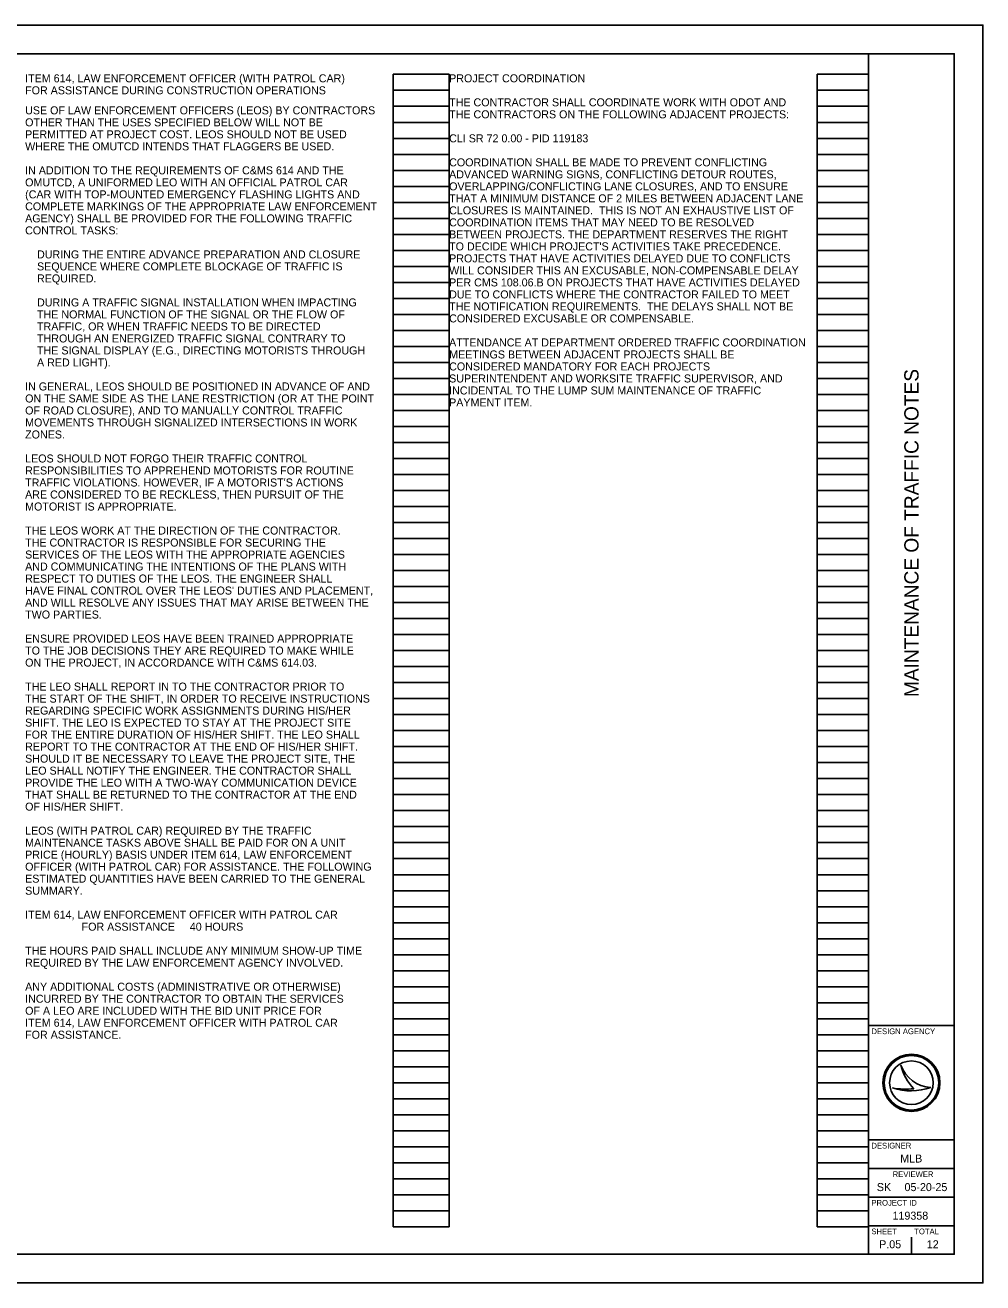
# Model space of a CAD drawing. Extents: x 0 to 34, y 0 to 22.
# Drawn here: x 17.24 to 34, y 0 to 22 of the extents above; entities that cross this region are included whole.
import ezdxf

# ---------------------------------------------------------------- set-up
doc = ezdxf.new("R2010")
doc.units = 0
for name, color, linetype in [('SH_Border', 7, 'Continuous'), ('SH_Cut_Line', 7, 'Continuous'), ('SH_Data', 7, 'Continuous'), ('SH_Text', 7, 'Continuous')]:
    doc.layers.add(name, color=color, linetype=linetype)

msp = doc.modelspace()

# ---------------------------------------------------------------- linework, layer by layer
at = {"layer": 'SH_Border'}
for p, q in [((32, 0.5), (32, 21.5)), ((32, 4.5), (33.5, 4.5)), ((32, 2.5), (33.5, 2.5)), ((32, 2), (33.5, 2)), ((32, 1.5), (33.5, 1.5)), ((32, 1), (33.5, 1))]:
    msp.add_line(p, q, dxfattribs=at)
msp.add_lwpolyline([(1.5, 21.5), (33.5, 21.5), (33.5, 0.5), (1.5, 0.5)], close=True, dxfattribs=at)
at = {"layer": 'SH_Cut_Line'}
msp.add_lwpolyline([(0, 0), (34, 0), (34, 22), (0, 22)], close=True, dxfattribs=at)
at = {"layer": 'SH_Data'}
for p, q in [((23.68, 0.98), (23.68, 21.14)), ((23.68, 21.14), (24.66, 21.14)), ((24.66, 0.98), (24.66, 21.14)), ((31.1, 0.98), (31.1, 21.14)), ((31.1, 21.14), (32, 21.14)), ((32, 0.98), (32, 21.14)), ((23.68, 20.86), (24.66, 20.86)), ((31.1, 20.86), (32, 20.86)), ((23.68, 20.58), (24.66, 20.58)), ((31.1, 20.58), (32, 20.58)), ((23.68, 20.3), (24.66, 20.3)), ((31.1, 20.3), (32, 20.3)), ((23.68, 20.02), (24.66, 20.02)), ((31.1, 20.02), (32, 20.02)), ((23.68, 19.74), (24.66, 19.74)), ((31.1, 19.74), (32, 19.74)), ((23.68, 19.46), (24.66, 19.46)), ((31.1, 19.46), (32, 19.46)), ((23.68, 19.18), (24.66, 19.18)), ((31.1, 19.18), (32, 19.18)), ((23.68, 18.9), (24.66, 18.9)), ((31.1, 18.9), (32, 18.9)), ((23.68, 18.62), (24.66, 18.62)), ((31.1, 18.62), (32, 18.62)), ((23.68, 18.34), (24.66, 18.34)), ((31.1, 18.34), (32, 18.34)), ((23.68, 18.06), (24.66, 18.06)), ((31.1, 18.06), (32, 18.06)), ((23.68, 17.78), (24.66, 17.78)), ((31.1, 17.78), (32, 17.78)), ((23.68, 17.5), (24.66, 17.5)), ((31.1, 17.5), (32, 17.5)), ((23.68, 17.22), (24.66, 17.22)), ((31.1, 17.22), (32, 17.22)), ((23.68, 16.94), (24.66, 16.94)), ((31.1, 16.94), (32, 16.94)), ((23.68, 16.66), (24.66, 16.66)), ((31.1, 16.66), (32, 16.66)), ((23.68, 16.38), (24.66, 16.38)), ((31.1, 16.38), (32, 16.38)), ((23.68, 16.1), (24.66, 16.1)), ((31.1, 16.1), (32, 16.1)), ((23.68, 15.82), (24.66, 15.82)), ((31.1, 15.82), (32, 15.82)), ((23.68, 15.54), (24.66, 15.54)), ((31.1, 15.54), (32, 15.54)), ((23.68, 15.26), (24.66, 15.26)), ((31.1, 15.26), (32, 15.26)), ((23.68, 14.98), (24.66, 14.98)), ((31.1, 14.98), (32, 14.98)), ((23.68, 14.7), (24.66, 14.7)), ((31.1, 14.7), (32, 14.7)), ((23.68, 14.42), (24.66, 14.42)), ((31.1, 14.42), (32, 14.42)), ((23.68, 14.14), (24.66, 14.14)), ((31.1, 14.14), (32, 14.14)), ((23.68, 13.86), (24.66, 13.86)), ((31.1, 13.86), (32, 13.86)), ((23.68, 13.58), (24.66, 13.58)), ((31.1, 13.58), (32, 13.58)), ((23.68, 13.3), (24.66, 13.3)), ((31.1, 13.3), (32, 13.3)), ((23.68, 13.02), (24.66, 13.02)), ((31.1, 13.02), (32, 13.02)), ((23.68, 12.74), (24.66, 12.74)), ((31.1, 12.74), (32, 12.74)), ((23.68, 12.46), (24.66, 12.46)), ((31.1, 12.46), (32, 12.46)), ((23.68, 12.18), (24.66, 12.18)), ((31.1, 12.18), (32, 12.18)), ((23.68, 11.9), (24.66, 11.9)), ((31.1, 11.9), (32, 11.9)), ((23.68, 11.62), (24.66, 11.62)), ((31.1, 11.62), (32, 11.62)), ((23.68, 11.34), (24.66, 11.34)), ((31.1, 11.34), (32, 11.34)), ((23.68, 11.06), (24.66, 11.06)), ((31.1, 11.06), (32, 11.06)), ((23.68, 10.78), (24.66, 10.78)), ((31.1, 10.78), (32, 10.78)), ((23.68, 10.5), (24.66, 10.5)), ((31.1, 10.5), (32, 10.5)), ((23.68, 10.22), (24.66, 10.22)), ((31.1, 10.22), (32, 10.22)), ((23.68, 9.94), (24.66, 9.94)), ((31.1, 9.94), (32, 9.94)), ((23.68, 9.66), (24.66, 9.66)), ((31.1, 9.66), (32, 9.66)), ((23.68, 9.38), (24.66, 9.38)), ((31.1, 9.38), (32, 9.38)), ((23.68, 9.1), (24.66, 9.1)), ((31.1, 9.1), (32, 9.1)), ((23.68, 8.82), (24.66, 8.82)), ((31.1, 8.82), (32, 8.82)), ((23.68, 8.54), (24.66, 8.54)), ((31.1, 8.54), (32, 8.54)), ((23.68, 8.26), (24.66, 8.26)), ((31.1, 8.26), (32, 8.26)), ((23.68, 7.98), (24.66, 7.98)), ((31.1, 7.98), (32, 7.98)), ((23.68, 7.7), (24.66, 7.7)), ((31.1, 7.7), (32, 7.7)), ((23.68, 7.42), (24.66, 7.42)), ((31.1, 7.42), (32, 7.42)), ((23.68, 7.14), (24.66, 7.14)), ((31.1, 7.14), (32, 7.14)), ((23.68, 6.86), (24.66, 6.86)), ((31.1, 6.86), (32, 6.86)), ((23.68, 6.58), (24.66, 6.58)), ((31.1, 6.58), (32, 6.58)), ((23.68, 6.3), (24.66, 6.3)), ((31.1, 6.3), (32, 6.3)), ((23.68, 6.02), (24.66, 6.02)), ((31.1, 6.02), (32, 6.02)), ((23.68, 5.74), (24.66, 5.74)), ((31.1, 5.74), (32, 5.74)), ((23.68, 5.46), (24.66, 5.46)), ((31.1, 5.46), (32, 5.46)), ((23.68, 5.18), (24.66, 5.18)), ((31.1, 5.18), (32, 5.18)), ((23.68, 4.9), (24.66, 4.9)), ((31.1, 4.9), (32, 4.9)), ((23.68, 4.62), (24.66, 4.62)), ((31.1, 4.62), (32, 4.62)), ((23.68, 4.34), (24.66, 4.34)), ((31.1, 4.34), (32, 4.34)), ((23.68, 4.06), (24.66, 4.06)), ((31.1, 4.06), (32, 4.06)), ((23.68, 3.78), (24.66, 3.78)), ((31.1, 3.78), (32, 3.78)), ((32.567, 3.81), (32.567, 3.81)), ((23.68, 3.5), (24.66, 3.5)), ((31.1, 3.5), (32, 3.5)), ((32.417, 3.41), (32.417, 3.41)), ((32.75, 3.5), (32.75, 3.5)), ((33.087, 3.419), (33.087, 3.419)), ((23.68, 3.22), (24.66, 3.22)), ((31.1, 3.22), (32, 3.22)), ((23.68, 2.94), (24.66, 2.94)), ((31.1, 2.94), (32, 2.94)), ((23.68, 2.66), (24.66, 2.66)), ((31.1, 2.66), (32, 2.66)), ((23.68, 2.38), (24.66, 2.38)), ((31.1, 2.38), (32, 2.38)), ((23.68, 2.1), (24.66, 2.1)), ((31.1, 2.1), (32, 2.1)), ((23.68, 1.82), (24.66, 1.82)), ((31.1, 1.82), (32, 1.82)), ((23.68, 1.54), (24.66, 1.54)), ((31.1, 1.54), (32, 1.54)), ((23.68, 1.26), (24.66, 1.26)), ((31.1, 1.26), (32, 1.26)), ((23.68, 0.98), (24.66, 0.98)), ((31.1, 0.98), (32, 0.98)), ((32.375, 0.675), (32.375, 0.675)), ((32.75, 0.5), (32.75, 0.8))]:
    msp.add_line(p, q, dxfattribs=at)
for radius in [0.5, 0.477, 0.477, 0.382]:
    msp.add_circle((32.75, 3.5), radius, dxfattribs=at)
for centre, radius, start, end in [((33.116, 3.998), 0.58, 198.9257, 198.9319), ((33.347, 3.97), 0.796, 191.6379, 191.6421), ((33.116, 3.998), 0.58, 198.9319, 267.1657), ((33.347, 3.97), 0.796, 191.6421, 226.0947), ((32.739, 4.37), 1.013, 251.4576, 290.0832), ((32.648, 4.654), 1.266, 259.4964, 259.4995), ((32.739, 4.37), 1.013, 251.4527, 251.4576), ((32.648, 4.654), 1.266, 259.4995, 276.6672)]:
    msp.add_arc(centre, radius, start, end, dxfattribs=at)

# ---------------------------------------------------------------- texts
msp.add_text('MAINTENANCE OF TRAFFIC NOTES', height=0.25, rotation=90, dxfattribs=at).set_placement((32.875, 10.247))
for s, height, p in [('DESIGN AGENCY', 0.1, (32.05, 4.35)), ('DESIGNER', 0.1, (32.05, 2.35)), ('MLB', 0.14, (32.554, 2.105)), ('REVIEWER', 0.1, (32.422, 1.85)), ('SK', 0.14, (32.145, 1.605)), ('05-20-25', 0.14, (32.629, 1.605)), ('PROJECT ID', 0.1, (32.05, 1.35)), ('119358', 0.14, (32.419, 1.105)), ('SHEET', 0.1, (32.05, 0.85)), ('TOTAL', 0.1, (32.8, 0.85)), ('P.05', 0.14, (32.185, 0.605)), ('12', 0.14, (33.019, 0.605))]:
    msp.add_text(s, height=height, dxfattribs=at).set_placement(p)
at = {"layer": 'SH_Text'}
for s, p in [('ITEM 614, LAW ENFORCEMENT OFFICER (WITH PATROL CAR)', (17.24, 21)), ('PROJECT COORDINATION', (24.66, 21)), ('FOR ASSISTANCE DURING CONSTRUCTION OPERATIONS', (17.24, 20.79)), ('THE CONTRACTOR SHALL COORDINATE WORK WITH ODOT AND ', (24.66, 20.58)), ('USE OF LAW ENFORCEMENT OFFICERS (LEOS) BY CONTRACTORS', (17.24, 20.44)), ('THE CONTRACTORS ON THE FOLLOWING ADJACENT PROJECTS:', (24.66, 20.37)), ('OTHER THAN THE USES SPECIFIED BELOW WILL NOT BE', (17.24, 20.23)), ('PERMITTED AT PROJECT COST. LEOS SHOULD NOT BE USED', (17.24, 20.02)), ('CLI SR 72 0.00 - PID 119183', (24.66, 19.95)), ('WHERE THE OMUTCD INTENDS THAT FLAGGERS BE USED.', (17.24, 19.81)), ('COORDINATION SHALL BE MADE TO PREVENT CONFLICTING ', (24.66, 19.53)), ('IN ADDITION TO THE REQUIREMENTS OF C&MS 614 AND THE', (17.24, 19.39)), ('ADVANCED WARNING SIGNS, CONFLICTING DETOUR ROUTES, ', (24.66, 19.32)), ('OMUTCD, A UNIFORMED LEO WITH AN OFFICIAL PATROL CAR', (17.24, 19.18)), ('OVERLAPPING/CONFLICTING LANE CLOSURES, AND TO ENSURE ', (24.66, 19.11)), ('(CAR WITH TOP-MOUNTED EMERGENCY FLASHING LIGHTS AND', (17.24, 18.97)), ('THAT A MINIMUM DISTANCE OF 2 MILES BETWEEN ADJACENT LANE ', (24.66, 18.9)), ('COMPLETE MARKINGS OF THE APPROPRIATE LAW ENFORCEMENT', (17.24, 18.76)), ('CLOSURES IS MAINTAINED.  THIS IS NOT AN EXHAUSTIVE LIST OF ', (24.66, 18.69)), ('AGENCY) SHALL BE PROVIDED FOR THE FOLLOWING TRAFFIC', (17.24, 18.55)), ('CONTROL TASKS:', (17.24, 18.34)), ('COORDINATION ITEMS THAT MAY NEED TO BE RESOLVED ', (24.66, 18.48)), ('BETWEEN PROJECTS. THE DEPARTMENT RESERVES THE RIGHT ', (24.66, 18.27)), ('    DURING THE ENTIRE ADVANCE PREPARATION AND CLOSURE', (17.24, 17.92)), ("TO DECIDE WHICH PROJECT'S ACTIVITIES TAKE PRECEDENCE.  ", (24.66, 18.06)), ('    SEQUENCE WHERE COMPLETE BLOCKAGE OF TRAFFIC IS', (17.24, 17.71)), ('PROJECTS THAT HAVE ACTIVITIES DELAYED DUE TO CONFLICTS ', (24.66, 17.85)), ('    REQUIRED.', (17.24, 17.5)), ('WILL CONSIDER THIS AN EXCUSABLE, NON-COMPENSABLE DELAY ', (24.66, 17.64)), ('PER CMS 108.06.B ON PROJECTS THAT HAVE ACTIVITIES DELAYED ', (24.66, 17.43)), ('    DURING A TRAFFIC SIGNAL INSTALLATION WHEN IMPACTING', (17.24, 17.08)), ('DUE TO CONFLICTS WHERE THE CONTRACTOR FAILED TO MEET ', (24.66, 17.22)), ('    THE NORMAL FUNCTION OF THE SIGNAL OR THE FLOW OF', (17.24, 16.87)), ('THE NOTIFICATION REQUIREMENTS.  THE DELAYS SHALL NOT BE ', (24.66, 17.01)), ('CONSIDERED EXCUSABLE OR COMPENSABLE.', (24.66, 16.8)), ('    TRAFFIC, OR WHEN TRAFFIC NEEDS TO BE DIRECTED', (17.24, 16.66)), ('    THROUGH AN ENERGIZED TRAFFIC SIGNAL CONTRARY TO', (17.24, 16.45)), ('ATTENDANCE AT DEPARTMENT ORDERED TRAFFIC COORDINATION ', (24.66, 16.38)), ('    THE SIGNAL DISPLAY (E.G., DIRECTING MOTORISTS THROUGH', (17.24, 16.24)), ('MEETINGS BETWEEN ADJACENT PROJECTS SHALL BE ', (24.66, 16.17)), ('    A RED LIGHT).', (17.24, 16.03)), ('CONSIDERED MANDATORY FOR EACH PROJECTS ', (24.66, 15.96)), ('SUPERINTENDENT AND WORKSITE TRAFFIC SUPERVISOR, AND ', (24.66, 15.75)), ('IN GENERAL, LEOS SHOULD BE POSITIONED IN ADVANCE OF AND', (17.24, 15.61)), ('INCIDENTAL TO THE LUMP SUM MAINTENANCE OF TRAFFIC ', (24.66, 15.54)), ('ON THE SAME SIDE AS THE LANE RESTRICTION (OR AT THE POINT', (17.24, 15.4)), ('PAYMENT ITEM.', (24.66, 15.33)), ('OF ROAD CLOSURE), AND TO MANUALLY CONTROL TRAFFIC', (17.24, 15.19)), ('MOVEMENTS THROUGH SIGNALIZED INTERSECTIONS IN WORK', (17.24, 14.98)), ('ZONES.', (17.24, 14.77)), ('LEOS SHOULD NOT FORGO THEIR TRAFFIC CONTROL', (17.24, 14.35)), ('RESPONSIBILITIES TO APPREHEND MOTORISTS FOR ROUTINE', (17.24, 14.14)), ('ARE CONSIDERED TO BE RECKLESS, THEN PURSUIT OF THE', (17.24, 13.72)), ("TRAFFIC VIOLATIONS. HOWEVER, IF A MOTORIST'S ACTIONS", (17.24, 13.93)), ('MOTORIST IS APPROPRIATE.', (17.24, 13.51)), ('THE LEOS WORK AT THE DIRECTION OF THE CONTRACTOR.', (17.24, 13.09)), ('THE CONTRACTOR IS RESPONSIBLE FOR SECURING THE', (17.24, 12.88)), ('SERVICES OF THE LEOS WITH THE APPROPRIATE AGENCIES', (17.24, 12.67)), ('AND COMMUNICATING THE INTENTIONS OF THE PLANS WITH', (17.24, 12.46)), ('RESPECT TO DUTIES OF THE LEOS. THE ENGINEER SHALL', (17.24, 12.25)), ("HAVE FINAL CONTROL OVER THE LEOS' DUTIES AND PLACEMENT,", (17.24, 12.04)), ('AND WILL RESOLVE ANY ISSUES THAT MAY ARISE BETWEEN THE', (17.24, 11.83)), ('TWO PARTIES.', (17.24, 11.62)), ('ENSURE PROVIDED LEOS HAVE BEEN TRAINED APPROPRIATE', (17.24, 11.2)), ('TO THE JOB DECISIONS THEY ARE REQUIRED TO MAKE WHILE', (17.24, 10.99)), ('ON THE PROJECT, IN ACCORDANCE WITH C&MS 614.03.', (17.24, 10.78)), ('THE LEO SHALL REPORT IN TO THE CONTRACTOR PRIOR TO', (17.24, 10.36)), ('THE START OF THE SHIFT, IN ORDER TO RECEIVE INSTRUCTIONS', (17.24, 10.15)), ('REGARDING SPECIFIC WORK ASSIGNMENTS DURING HIS/HER', (17.24, 9.94)), ('SHIFT. THE LEO IS EXPECTED TO STAY AT THE PROJECT SITE', (17.24, 9.73)), ('FOR THE ENTIRE DURATION OF HIS/HER SHIFT. THE LEO SHALL', (17.24, 9.52)), ('SHOULD IT BE NECESSARY TO LEAVE THE PROJECT SITE, THE', (17.24, 9.1)), ('REPORT TO THE CONTRACTOR AT THE END OF HIS/HER SHIFT.', (17.24, 9.31)), ('LEO SHALL NOTIFY THE ENGINEER. THE CONTRACTOR SHALL', (17.24, 8.89)), ('PROVIDE THE LEO WITH A TWO-WAY COMMUNICATION DEVICE', (17.24, 8.68)), ('THAT SHALL BE RETURNED TO THE CONTRACTOR AT THE END', (17.24, 8.47)), ('OF HIS/HER SHIFT.', (17.24, 8.26)), ('LEOS (WITH PATROL CAR) REQUIRED BY THE TRAFFIC', (17.24, 7.84)), ('MAINTENANCE TASKS ABOVE SHALL BE PAID FOR ON A UNIT', (17.24, 7.63)), ('PRICE (HOURLY) BASIS UNDER ITEM 614, LAW ENFORCEMENT', (17.24, 7.42)), ('OFFICER (WITH PATROL CAR) FOR ASSISTANCE. THE FOLLOWING', (17.24, 7.21)), ('ESTIMATED QUANTITIES HAVE BEEN CARRIED TO THE GENERAL', (17.24, 7)), ('SUMMARY.', (17.24, 6.79)), ('ITEM 614, LAW ENFORCEMENT OFFICER WITH PATROL CAR', (17.24, 6.37)), ('                   FOR ASSISTANCE     40 HOURS', (17.24, 6.16)), ('THE HOURS PAID SHALL INCLUDE ANY MINIMUM SHOW-UP TIME', (17.24, 5.74)), ('REQUIRED BY THE LAW ENFORCEMENT AGENCY INVOLVED.', (17.24, 5.53)), ('ANY ADDITIONAL COSTS (ADMINISTRATIVE OR OTHERWISE)', (17.24, 5.11)), ('INCURRED BY THE CONTRACTOR TO OBTAIN THE SERVICES', (17.24, 4.9)), ('OF A LEO ARE INCLUDED WITH THE BID UNIT PRICE FOR', (17.24, 4.69)), ('ITEM 614, LAW ENFORCEMENT OFFICER WITH PATROL CAR', (17.24, 4.48)), ('FOR ASSISTANCE.', (17.24, 4.27))]:
    msp.add_text(s, height=0.14, dxfattribs=at).set_placement(p)

doc.saveas('drawing.dxf')
